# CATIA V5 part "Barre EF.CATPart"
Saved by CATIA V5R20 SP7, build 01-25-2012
Part number: Barre EF
Bounding box of the stored display mesh (mm): x -2 to 2, y -21.984 to -8.24, z 8.016 to 89.369
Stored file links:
  U:\IAO_bon\Barre EF.CATPart
  U:\IAO_bon\Cqueguiner_IAo.CATProduct
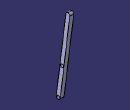
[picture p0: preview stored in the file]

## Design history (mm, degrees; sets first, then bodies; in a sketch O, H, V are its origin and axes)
Set1
  Line1 "Axe pivot EF/Bati": linked copy from another document
  Line2: linked copy from another document
  Point1 "Point E": linked copy from another document
  Point2 "Point F": linked copy from another document
Body1 (main body)
  Sketch1 on yz-plane, origin (0, 0, 0), H (0, 1, 0), V (0, 0, 1)
    line L1 (-11.9576, 89.6198) -> (-21.9842, 10.2507)
    arc A1 centre (-20, 10) radius 2 from (-21.9842, 10.2507) to (-18.0158, 9.7493) ccw
    point P3 (-20, 10)
    line L2 (-18.0158, 9.7493) -> (-7.9891, 89.1185)
    line L3 (-7.9891, 89.1185) -> (-11.9576, 89.6198)
    reference projected point E1 (-20, 10) from Line1
    reference projected line E2 (-20, 10) -> (-16.24, 39.7634) from Line2
    reference projected line E3 (-20, 10) -> (-16.24, 39.7634) from Line2
    reference projected point E4 (-20, 10) from Point1
    circle A2 centre (-20, 10) radius 1.5
    circle A3 centre (-16.24, 39.7634) radius 1.5
    point P6 (-16.24, 39.7634)
    reference projected point E5 (-16.24, 39.7634) from Point2
    radius A1 = 2
    angle L1 L3 = 90
    distance E4 L3 = 80
    radius A2 = 1.5
    radius A3 = 1.5
    tangency: A1 L1, L2 A1
    coincidence: E1 P3, P6 E5
    parallelism: E2 L1, L2 E3
  Pad1: profile Sketch1, direction (1, 0, 0), length 2, opposite side length 2
  Fillet1: radius 2, on face of Pad1 from Sketch1.L3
